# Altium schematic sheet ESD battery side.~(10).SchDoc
size A3; SheetNumber: 15; SheetTotal: 15
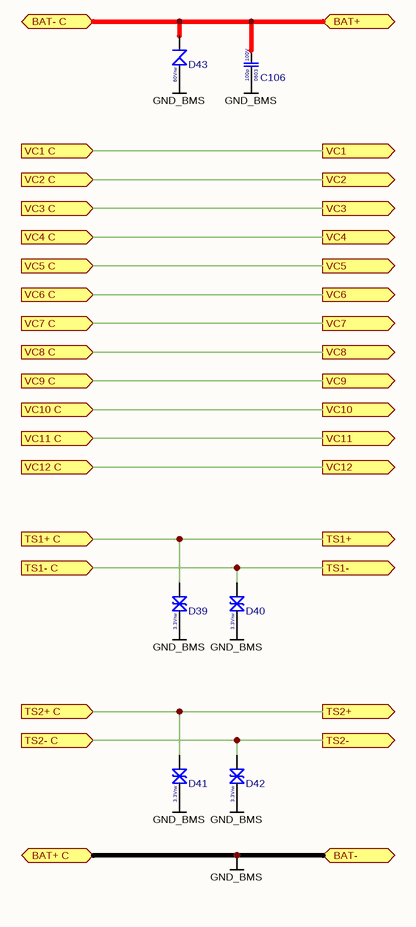
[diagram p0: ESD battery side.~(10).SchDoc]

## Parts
C106  Voltage Rating: 100V  Case Code (Imperial): 0603  Capacitance: 100p  [CAP 0603]  (hidden comment: CC0603JRNPO0BN101)
D39  V_RWM: 3.3Vrw  [SOD-523]  (hidden comment: H3V3LD5B)
D40  V_RWM: 3.3Vrw  [SOD-523]  (hidden comment: H3V3LD5B)
D41  V_RWM: 3.3Vrw  [SOD-523]  (hidden comment: H3V3LD5B)
D42  V_RWM: 3.3Vrw  [SOD-523]  (hidden comment: H3V3LD5B)
D43  Reverse Voltage: 60Vrw  [DO-214AA]  (hidden comment: SMBJ60A)

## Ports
BAT+ (bidir, see Arhitecture[2B], BAT+ to 5V1 STEP-DOWN[3B], BMS[1A], BQ34Z100 FUEL GAUGE[3A], BQ76952 BMS[1A], ESD system side[2A]), BAT+ C (bidir, see Arhitecture[2B]), BAT- (bidir, see Arhitecture[2C], BMS[1D]), BAT- C (bidir, see Arhitecture[2C]), TS1+ (out, see Arhitecture[2B], Charger BQ25756[2C], CHARGER[1B]), TS1+ C (in, see Arhitecture[2B]), TS1- (out, see Arhitecture[2B], Charger BQ25756[2C], CHARGER[1B]), TS1- C (in, see Arhitecture[2B]), TS2+ (out, see Arhitecture[2C], BMS[1C], BQ76952 BMS[3C]), TS2+ C (in, see Arhitecture[2C]), TS2- (out, see Arhitecture[2C], BMS[1C], BQ76952 BMS[3C]), TS2- C (in, see Arhitecture[2C]), VC1 (out, see Arhitecture[2B], BMS[1B], BQ76952 BMS[1C]), VC1 C (in, see Arhitecture[2B]), VC2 (out, see Arhitecture[2B], BMS[1B], BQ76952 BMS[1C]), VC2 C (in, see Arhitecture[2B]), VC3 (out, see Arhitecture[2B], BMS[1B], BQ76952 BMS[1C]), VC3 C (in, see Arhitecture[2B]), VC4 (out, see Arhitecture[2B], BMS[1B], BQ76952 BMS[1C]), VC4 C (in, see Arhitecture[2B]), VC5 (out, see Arhitecture[2B], BMS[1B], BQ76952 BMS[1C]), VC5 C (in, see Arhitecture[2B]), VC6 (out, see Arhitecture[2B], BMS[1B], BQ76952 BMS[1C]), VC6 C (in, see Arhitecture[2B]), VC7 (out, see Arhitecture[2B], BMS[1B], BQ76952 BMS[1C]), VC7 C (in, see Arhitecture[2B]), VC8 (out, see Arhitecture[2B], BMS[1B], BQ76952 BMS[1B]), VC8 C (in, see Arhitecture[2B]), VC9 (out, see Arhitecture[2B], BMS[1B], BQ76952 BMS[1B]), VC9 C (in, see Arhitecture[2B]), VC10 (out, see Arhitecture[2B], BMS[1B], BQ76952 BMS[1B]), VC10 C (in, see Arhitecture[2B]), VC11 (out, see Arhitecture[2B], BMS[1B], BQ76952 BMS[1B]), VC11 C (in, see Arhitecture[2B]), VC12 (out, see Arhitecture[2B], BMS[1B], BQ76952 BMS[1B]), VC12 C (in, see Arhitecture[2B])

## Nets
GND_BMS: C106.1 D39.K D40.K D41.K D42.K D43.A ; port BAT+ C, port BAT-
BAT+: C106.2 D43.K ; port BAT- C, port BAT+
TS1+: D39.A ; port TS1+ C, port TS1+
TS1-: D40.A ; port TS1- C, port TS1-
TS2+: D41.A ; port TS2+ C, port TS2+
TS2-: D42.A ; port TS2- C, port TS2-
VC1: port VC1 C, port VC1
VC2: port VC2 C, port VC2
VC3: port VC3 C, port VC3
VC4: port VC4 C, port VC4
VC5: port VC5 C, port VC5
VC6: port VC6 C, port VC6
VC7: port VC7 C, port VC7
VC8: port VC8 C, port VC8
VC9: port VC9 C, port VC9
VC10: port VC10 C, port VC10
VC11: port VC11 C, port VC11
VC12: port VC12 C, port VC12

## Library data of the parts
C106 = CC0603JRNPO0BN101: Cap 100pF 100V 0603 NP0; Manufacturer: Yageo; Manufacturer Part Number: CC0603KRX7R9BB104
D39-D42 = H3V3LD5B: ESD TVS 3.3Vrw 0.2uA 12.5pF; Manufacturer: hongjiacheng
D43 = SMBJ60A: TVS ESD Zener UniD 60Vrw 1uA; Manufacturer: Shandong Jingdao Microelectronics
